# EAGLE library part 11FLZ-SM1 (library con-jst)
CONNECTOR
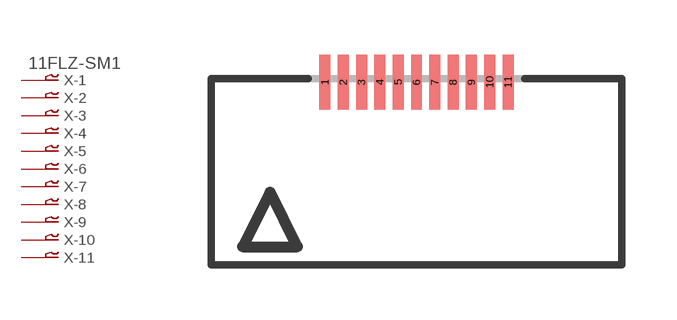
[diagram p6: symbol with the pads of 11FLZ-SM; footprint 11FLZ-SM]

Designator prefix X; gates -1=P-VN -2=P-N -3=P-N -4=P-N -5=P-N -6=P-N -7=P-N -8=P-N -9=P-N -10=P-N -11=P-N

## 11FLZ-SM1 (OC_FARNELL: unknown; OC_NEWARK: unknown)  [11FLZ-SM]
1  -1:1  pas
2  -2:1  pas
3  -3:1  pas
4  -4:1  pas
5  -5:1  pas
6  -6:1  pas
7  -7:1  pas
8  -8:1  pas
9  -9:1  pas
10  -10:1  pas
11  -11:1  pas

## Footprint 11FLZ-SM (pad centres in mm)
CONNECTOR
smd 0.3 x 1.5: 1 -2.5,2.5; 2 -2,2.5; 3 -1.5,2.5; 4 -1,2.5; 5 -0.5,2.5; 6 0,2.5; 7 0.5,2.5; 8 1,2.5; 9 1.5,2.5; 10 2,2.5; 11 2.5,2.5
